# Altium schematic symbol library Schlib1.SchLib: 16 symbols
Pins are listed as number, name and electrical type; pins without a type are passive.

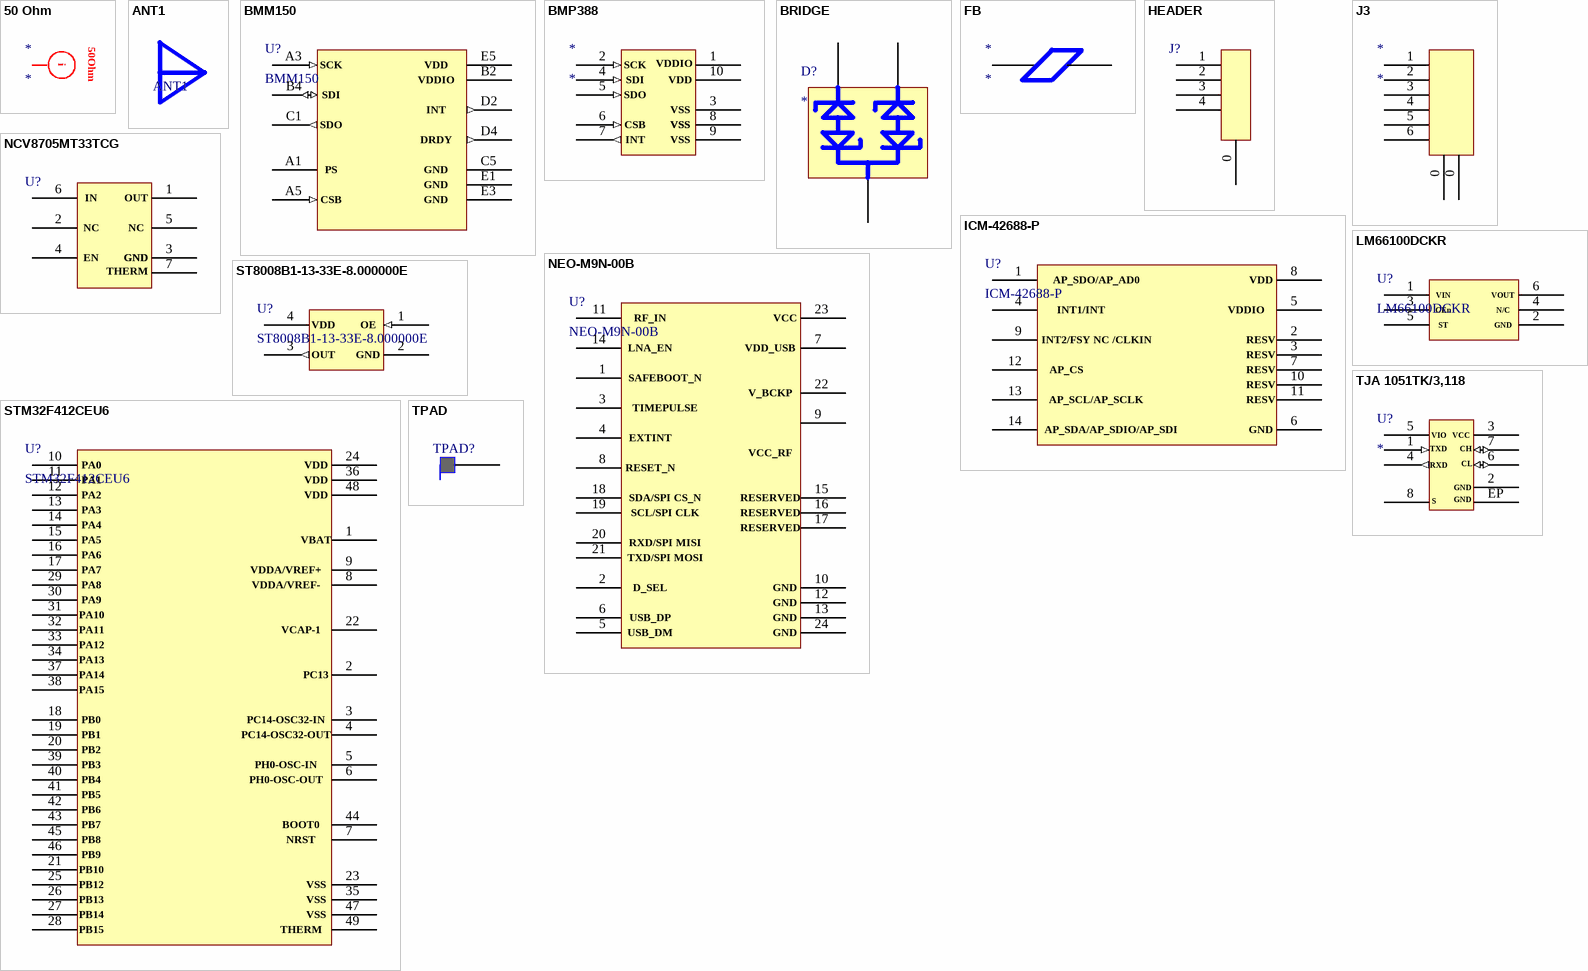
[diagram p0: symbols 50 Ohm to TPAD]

## 50 Ohm
designator *

## ANT1
designator ?

## BMM150
designator U?
pins: A1, A3 (in), A5 (in), B2, B4 (io), C1 (out), C5, D2 (out), D4 (out), E1, E3, E5

## BMP388
designator *
pins: 1, 2 (in), 3, 4 (in), 5 (in), 6 (in), 7 (out), 8, 9, 10

## BRIDGE
designator D?
pins: 1, 2, 3

## FB
designator *
pins: 1, 2

## HEADER
designator J?  (value not drawn)
pins: 0, 1, 2, 3, 4

## ICM-42688-P
designator U?
pins: 1, 2, 3, 4, 5, 6, 7, 8, 9, 10, 11, 12, 13, 14

## J3
designator *
pins: 0, 0, 1, 2, 3, 4, 5, 6

## LM66100DCKR
designator U?
pins: 1, 2, 3, 4, 5, 6

## NCV8705MT33TCG
designator U?  (value not drawn)
pins: 1, 2, 3, 4, 5, 6, 7

## NEO-M9N-00B
designator U?
pins: 1, 2, 3, 4, 5, 6, 7, 8, 9, 10, 11, 12, 13, 14, 15 10, 16 11, 17 12, 18, 19, 20, 21, 22, 23, 24

## ST8008B1-13-33E-8.000000E
designator U?
pins: 1 (in), 2, 3 (out), 4 50

## STM32F412CEU6
designator U?
pins: 1, 2, 3, 4, 5, 6, 7, 8, 9, 10, 11, 12, 13, 14, 15, 16, 17, 18, 19, 20, 21, 22, 23, 24, 25, 26, 27, 28, 29, 30, 31, 32, 33, 34, 35, 36, 37, 38, 39, 40, 41, 42, 43, 44, 45, 46, 47, 48, 49

## TJA 1051TK/3,118
designator U?
pins: 1 (in), 2, 3, 4 (out), 5, 6 (io), 7 (io), 8, EP

## TPAD
designator TPAD?  (value not drawn)
pins: 1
